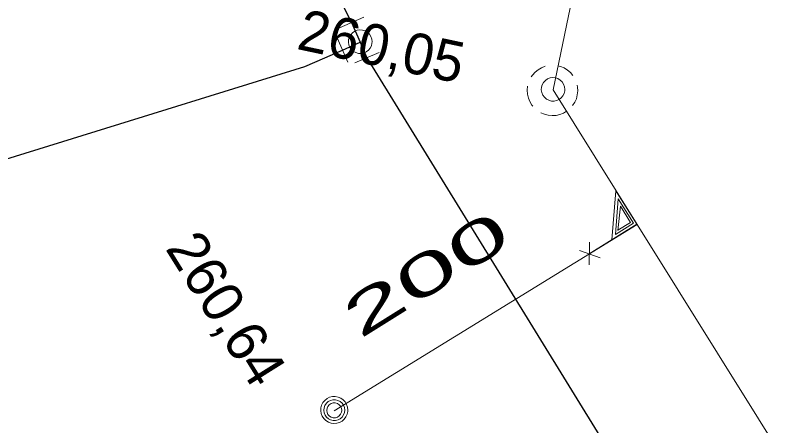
# Model space of a CAD drawing. Extents: x -732074 to -731966, y -1048695 to -1047982.
# Drawn here: x -732032.71 to -732017.44, y -1048092.2 to -1048084.19 of the extents above; entities that cross this region are included whole.
import ezdxf

# ---------------------------------------------------------------- set-up
doc = ezdxf.new("R2010")
doc.units = 0
doc.header["$LTSCALE"] = 0.32
doc.layers.add('1', color=7, linetype='Continuous')
for name, color, linetype, lineweight in [('18', 7, 'Continuous', 13), ('20', 7, 'Continuous', 13), ('49', 7, 'Continuous', 13), ('8', 7, 'Continuous', 13)]:
    doc.layers.add(name, color=color, linetype=linetype, lineweight=lineweight)

msp = doc.modelspace()

# ---------------------------------------------------------------- linework, layer by layer
at = {"layer": '18'}
for p, q in [((-732021.494, -1048089.06), (-732021.484, -1048088.616)), ((-732021.685, -1048088.779), (-732021.279, -1048088.921))]:
    msp.add_line(p, q, dxfattribs=at)
for points in [[(-732022.352, -1048085.177), (-732022.423, -1048085.205), (-732022.49, -1048085.244), (-732022.55, -1048085.292), (-732022.601, -1048085.349), (-732022.625, -1048085.383)], [(-732021.811, -1048085.36), (-732021.861, -1048085.302), (-732021.919, -1048085.252), (-732021.984, -1048085.211), (-732022.055, -1048085.182), (-732022.104, -1048085.168)], [(-732022.697, -1048085.569), (-732022.703, -1048085.646), (-732022.698, -1048085.723), (-732022.681, -1048085.798), (-732022.652, -1048085.869), (-732022.612, -1048085.935), (-732022.596, -1048085.957)], [(-732021.816, -1048085.946), (-732021.775, -1048085.881), (-732021.744, -1048085.811), (-732021.725, -1048085.736), (-732021.717, -1048085.66), (-732021.722, -1048085.583), (-732021.728, -1048085.548)], [(-732022.439, -1048086.086), (-732022.369, -1048086.117), (-732022.294, -1048086.136), (-732022.218, -1048086.143), (-732022.141, -1048086.138), (-732022.066, -1048086.121), (-732021.994, -1048086.093), (-732021.934, -1048086.058)], [(-732021.49, -1048088.847), (-732020.561, -1048088.267), (-732020.969, -1048087.613), (-732021.051, -1048088.573)], [(-732020.978, -1048088.467), (-732020.625, -1048088.247), (-732020.925, -1048087.768), (-732020.979, -1048088.468)], [(-732020.932, -1048088.383), (-732020.685, -1048088.229), (-732020.881, -1048087.914), (-732020.931, -1048088.385)]]:
    msp.add_lwpolyline(points, dxfattribs=at)
for points in [[(-732021.968, -1048085.629), (-732021.974, -1048085.577), (-732021.992, -1048085.527), (-732022.02, -1048085.483), (-732022.058, -1048085.446), (-732022.103, -1048085.419), (-732022.153, -1048085.403), (-732022.205, -1048085.398), (-732022.257, -1048085.405), (-732022.306, -1048085.424), (-732022.35, -1048085.454), (-732022.385, -1048085.493), (-732022.411, -1048085.538), (-732022.426, -1048085.589), (-732022.429, -1048085.641), (-732022.421, -1048085.693), (-732022.4, -1048085.741), (-732022.37, -1048085.784), (-732022.33, -1048085.819), (-732022.284, -1048085.843), (-732022.233, -1048085.857), (-732022.181, -1048085.859), (-732022.129, -1048085.849), (-732022.081, -1048085.827), (-732022.039, -1048085.795), (-732022.006, -1048085.755), (-732021.982, -1048085.708), (-732021.97, -1048085.657)], [(-732026.216, -1048091.897), (-732026.222, -1048091.841), (-732026.239, -1048091.788), (-732026.267, -1048091.739), (-732026.306, -1048091.698), (-732026.352, -1048091.666), (-732026.404, -1048091.644), (-732026.459, -1048091.633), (-732026.515, -1048091.635), (-732026.57, -1048091.648), (-732026.62, -1048091.673), (-732026.665, -1048091.708), (-732026.701, -1048091.751), (-732026.726, -1048091.801), (-732026.741, -1048091.856), (-732026.744, -1048091.912), (-732026.735, -1048091.967), (-732026.714, -1048092.02), (-732026.683, -1048092.066), (-732026.642, -1048092.105), (-732026.595, -1048092.135), (-732026.542, -1048092.154), (-732026.486, -1048092.161), (-732026.429, -1048092.157), (-732026.375, -1048092.14), (-732026.326, -1048092.113), (-732026.285, -1048092.075), (-732026.252, -1048092.03), (-732026.228, -1048091.979), (-732026.217, -1048091.924)], [(-732026.275, -1048091.9), (-732026.281, -1048091.851), (-732026.299, -1048091.805), (-732026.326, -1048091.764), (-732026.364, -1048091.731), (-732026.407, -1048091.709), (-732026.456, -1048091.697), (-732026.505, -1048091.697), (-732026.553, -1048091.709), (-732026.597, -1048091.732), (-732026.634, -1048091.765), (-732026.662, -1048091.806), (-732026.679, -1048091.853), (-732026.684, -1048091.902), (-732026.678, -1048091.951), (-732026.66, -1048091.997), (-732026.632, -1048092.037), (-732026.595, -1048092.07), (-732026.551, -1048092.092), (-732026.502, -1048092.104), (-732026.453, -1048092.103), (-732026.405, -1048092.091), (-732026.362, -1048092.067), (-732026.325, -1048092.034), (-732026.297, -1048091.993), (-732026.281, -1048091.946)], [(-732026.334, -1048091.904), (-732026.34, -1048091.862), (-732026.357, -1048091.824), (-732026.385, -1048091.793), (-732026.419, -1048091.77), (-732026.46, -1048091.759), (-732026.502, -1048091.759), (-732026.542, -1048091.771), (-732026.576, -1048091.794), (-732026.603, -1048091.826), (-732026.62, -1048091.864), (-732026.625, -1048091.905), (-732026.62, -1048091.947), (-732026.602, -1048091.984), (-732026.574, -1048092.016), (-732026.538, -1048092.038), (-732026.498, -1048092.049), (-732026.456, -1048092.048), (-732026.416, -1048092.035), (-732026.382, -1048092.012), (-732026.355, -1048091.979), (-732026.339, -1048091.941)]]:
    msp.add_lwpolyline(points, close=True, dxfattribs=at)
at = {"layer": '20'}
msp.add_line((-732022.199, -1048085.64), (-732020.059, -1048075.41), dxfattribs=at)
msp.add_line((-732022.199, -1048085.64), (-732020.059, -1048075.41), dxfattribs=at)
msp.add_lwpolyline([(-731999.239, -1048122.39), (-732003.535, -1048115.515), (-732011.701, -1048102.444), (-732015.041, -1048097.097), (-732020.556, -1048088.271), (-732022.199, -1048085.64)], dxfattribs=at)
msp.add_lwpolyline([(-731999.239, -1048122.39), (-732003.535, -1048115.515), (-732011.701, -1048102.444), (-732015.041, -1048097.097), (-732020.556, -1048088.271), (-732022.199, -1048085.64)], dxfattribs=at)
at = {"layer": '49'}
msp.add_line((-732026.48, -1048091.91), (-732020.556, -1048088.271), dxfattribs=at)
msp.add_line((-732026.48, -1048091.91), (-732020.556, -1048088.271), dxfattribs=at)
at = {"layer": '8', "lineweight": 25}
for p, q in [((-732028.59, -1048079.49), (-732026.14, -1048084.32)), ((-732026.14, -1048084.32), (-732025.971, -1048084.708)), ((-732026.32, -1048084.86), (-732025.971, -1048084.708)), ((-732025.971, -1048084.708), (-732025.84, -1048085.01))]:
    msp.add_line(p, q, dxfattribs=at)
at = {"layer": '8'}
for p, q in [((-732026.376, -1048084.423), (-732025.903, -1048084.215)), ((-732026.215, -1048085.096), (-732026.421, -1048084.622)), ((-732025.601, -1048084.906), (-732026.076, -1048085.112))]:
    msp.add_line(p, q, dxfattribs=at)
msp.add_lwpolyline([(-732025.74, -1048084.697), (-732025.746, -1048084.645), (-732025.764, -1048084.595), (-732025.792, -1048084.551), (-732025.83, -1048084.514), (-732025.875, -1048084.487), (-732025.925, -1048084.471), (-732025.977, -1048084.466), (-732026.029, -1048084.473), (-732026.078, -1048084.492), (-732026.122, -1048084.522), (-732026.157, -1048084.561), (-732026.183, -1048084.606), (-732026.198, -1048084.657), (-732026.201, -1048084.709), (-732026.193, -1048084.761), (-732026.172, -1048084.809), (-732026.142, -1048084.852), (-732026.102, -1048084.887), (-732026.056, -1048084.911), (-732026.005, -1048084.925), (-732025.953, -1048084.927), (-732025.901, -1048084.917), (-732025.853, -1048084.895), (-732025.811, -1048084.863), (-732025.778, -1048084.823), (-732025.754, -1048084.776), (-732025.742, -1048084.725)], close=True, dxfattribs=at)
at = {"layer": '8', "lineweight": 25}
for points in [[(-732040.697, -1048089.406), (-732027.052, -1048085.18), (-732026.32, -1048084.86)], [(-732025.84, -1048085.01), (-732021.18, -1048092.58), (-732017.71, -1048097.66)]]:
    msp.add_lwpolyline(points, dxfattribs=at)

# ---------------------------------------------------------------- texts
at = {"layer": '1'}
for s, rotation, p in [('260,05', 348, (-732027.237, -1048084.835)), ('260,64', 302, (-732029.796, -1048088.738))]:
    msp.add_text(s, height=0.8, rotation=rotation, dxfattribs=at).set_placement(p)
at = {"layer": '1', "width": 2}
msp.add_text('200 ', height=0.8, rotation=32, dxfattribs=at).set_placement((-732025.983, -1048090.521))

doc.saveas('drawing.dxf')
